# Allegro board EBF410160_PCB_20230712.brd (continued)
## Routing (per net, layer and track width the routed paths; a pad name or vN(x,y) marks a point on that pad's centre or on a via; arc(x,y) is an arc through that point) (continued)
UART9_RX_M1: length 97.9
  TOP w0.156: R225.2 v1(111.38,22.35) ; v1(53.63,59.09) 54.13,59.59 J7.21
  BOTTOM w0.156: v1(111.38,22.35) 109.73,20.7 109.73,15.49 109.09,14.86 80.77,14.86 80.01,15.62 80.01,19.43 79.25,20.19 79.25,23.62 61.59,41.27 59.69,41.27 52.7,48.26 52.7,57.4 53.63,58.33 v1(53.63,59.09)
UART9_TX_M1: length 95.9
  TOP w0.156: J7.19 v1(53.63,60.11) ; R226.2 v1(110.36,22.35)
  BOTTOM w0.156: v1(53.63,60.11) 54.11,59.63 54.11,58.18 53.15,57.21 53.15,48.57 60.03,41.7 61.9,41.7 79.88,23.73 79.88,20.32 80.64,19.55 80.64,15.87 81.15,15.37 108.84,15.37 109.22,15.75 109.22,21.21 v1(110.36,22.35)
USB2_HOST2_DM: length 45.1
  TOP w0.158: v1(92.48,33.4) 92.25,33.17 92.25,32.42 92.49,32.18 93.15,32.18 R126.1 ; J7.74 67.13,56.46 67.06,56.39 67.06,48.39 67.34,48.1 67.34,47.37 v1(67.46,47.24)
  BOTTOM w0.158: v1(67.46,47.24) 71.63,47.24 74.03,44.85 arc(74.12,44.81) 74.21,44.85 arc(74.31,44.89) 74.4,44.85 74.66,44.59 arc(74.7,44.5) 74.66,44.4 arc(74.62,44.31) 74.66,44.21 82.68,36.19 90.3,36.19 90.45,36.04 arc(90.55,36) 90.64,36.04 arc(90.74,36.08) 90.83,36.04 91.09,35.78 arc(91.13,35.69) 91.09,35.59 arc(91.05,35.5) 91.09,35.4 91.35,35.14 arc(91.44,35.11) 91.54,35.14 arc(91.63,35.18) 91.73,35.14 91.99,34.89 arc(92.02,34.79) 91.99,34.7 arc(91.95,34.6) 91.99,34.51 92.31,34.19 92.31,33.57 v1(92.48,33.4)
USB2_HOST2_DP: length 45.1
  TOP w0.158: v1(91.82,33.4) 91.89,33.33 91.89,32.27 92.34,31.82 93.15,31.82 R125.1 ; J7.72 66.63,56.43 66.69,56.37 66.69,48.24 66.98,47.95 66.98,47.42 v1(66.8,47.24)
  BOTTOM w0.158: v1(91.82,33.4) 91.95,33.53 91.95,34.04 90.15,35.83 82.53,35.83 71.48,46.88 67.79,46.88 67.67,46.76 67.26,46.76 66.98,47.04 66.98,47.07 v1(66.8,47.24)
USB2_HOST3_DM: length 45.8
  TOP w0.158: R142.2 98.41,48.37 97.49,48.37 arc(97.39,48.41) 97.35,48.5 arc(97.31,48.6) 97.21,48.64 96.85,48.64 arc(96.76,48.6) 96.72,48.5 arc(96.68,48.41) 96.58,48.37 90.4,48.37 89.92,47.88 70.36,47.88 69.09,46.61 65.91,46.61 65.56,46.96 65.56,52.78 arc(65.59,52.86) 65.67,52.89 arc(65.75,52.92) 65.79,53 65.79,53.41 arc(65.75,53.49) 65.67,53.52 arc(65.59,53.56) 65.56,53.63 65.56,54.04 arc(65.59,54.12) 65.67,54.15 arc(65.75,54.19) 65.79,54.27 65.79,54.68 arc(65.75,54.75) 65.67,54.79 arc(65.59,54.82) 65.56,54.9 65.56,56.3 65.63,56.37 J7.68
USB2_HOST3_DP: length 45.5
  TOP w0.158: R141.2 98.56,48 90.55,48 90.07,47.52 70.51,47.52 69.24,46.25 65.76,46.25 65.2,46.81 65.2,56.3 65.13,56.37 J7.66
USB3_HOST1_DM: length 89.2
  TOP w0.158: v1(93.98,41.2) 93.85,41.07 93.85,40.51 93.47,40.13 92.45,40.13 92.05,40.53 78.63,40.53 70.74,32.64 48.64,32.64 43.56,27.55 43.56,25.94 43.63,25.87 J4.80
  BOTTOM w0.158: v1(93.98,41.2) 93.85,41.33 93.85,45.08 97.9,49.13 97.9,62.76 94.87,65.78 94.87,67.19 R136.2
USB3_HOST1_DP: length 89.2
  TOP w0.158: v1(93.32,41.2) 93.49,41.03 93.49,40.66 93.32,40.49 92.6,40.49 92.2,40.89 78.48,40.89 70.59,33 48.49,33 43.2,27.7 43.2,25.94 43.13,25.87 J4.78
  BOTTOM w0.158: v1(93.32,41.2) 93.49,41.37 93.49,45.23 97.54,49.28 97.54,62.61 94.51,65.64 94.51,67.3 R137.2
USB3_HOST1_SSRXN: length 107.4
  TOP w0.158: v1(90.42,42.8) 90.55,42.93 90.55,43.17 90.39,43.33 78.12,43.33 69.6,34.8 43.13,34.8 38.56,30.23 38.56,29.94 arc(38.6,29.83) 38.71,29.79 arc(38.82,29.75) 38.86,29.64 38.86,29.31 arc(38.82,29.2) 38.71,29.16 arc(38.6,29.11) 38.56,29.01 38.56,28.67 arc(38.6,28.57) 38.71,28.52 arc(38.82,28.48) 38.86,28.37 38.86,28.04 arc(38.82,27.93) 38.71,27.89 arc(38.6,27.85) 38.56,27.74 38.56,25.94 38.63,25.87 J4.60
  BOTTOM w0.158: v1(90.42,42.8) 90.6,42.97 90.6,44.12 96.54,50.06 96.54,56.49 95.89,57.15 95.89,62.23 94.74,63.37 arc(94.61,63.43) 94.48,63.37 arc(94.36,63.32) 94.23,63.37 94.04,63.57 arc(93.98,63.7) 94.04,63.82 arc(94.09,63.95) 94.04,64.07 92.9,65.21 92.9,70 92.83,70.07 U18.2 U18.9 92.83,71.67 92.97,71.81 92.97,73.02 91.67,74.31 90.92,74.31 90.45,74.78 90.45,76.38 90.91,76.85 90.91,77.49 90.45,77.96 90.45,78.71 90.29,78.87 J18.5
USB3_HOST1_SSRXP: length 107.4
  TOP w0.158: J4.58 38.13,25.87 38.2,25.94 38.2,30.37 42.98,35.16 69.45,35.16 77.97,43.69 90.56,43.69 90.93,43.32 90.93,42.95 v1(91.08,42.8)
  BOTTOM w0.158: v1(91.08,42.8) 90.96,42.92 90.96,43.97 96.9,49.91 96.9,56.64 96.25,57.3 96.25,62.38 93.26,65.36 93.26,70 93.33,70.07 U18.1 U18.10 93.33,73.17 91.82,74.67 91.07,74.67 90.81,74.93 90.81,76.23 91.27,76.7 91.27,77.64 90.81,78.1 90.81,78.62 91.06,78.87 J18.6
USB3_HOST1_SSTXN: length 95.4
  TOP w0.158: J4.64 39.63,25.87 39.56,25.94 39.56,27.03 40.09,27.56 arc(40.2,27.61) 40.31,27.56 arc(40.41,27.52) 40.52,27.56 40.75,27.8 arc(40.8,27.91) 40.75,28.01 arc(40.71,28.12) 40.75,28.23 40.99,28.46 arc(41.09,28.5) 41.2,28.46 arc(41.31,28.42) 41.42,28.46 41.65,28.69 arc(41.69,28.8) 41.65,28.91 arc(41.6,29.01) 41.65,29.12 41.88,29.36 arc(41.99,29.4) 42.1,29.36 arc(42.2,29.31) 42.31,29.36 42.54,29.59 arc(42.59,29.7) 42.54,29.8 arc(42.5,29.91) 42.54,30.02 42.75,30.22 arc(42.85,30.26) 42.96,30.22 arc(43.07,30.17) 43.17,30.22 43.41,30.45 arc(43.45,30.56) 43.41,30.67 arc(43.36,30.77) 43.41,30.88 46.33,33.8 70.25,33.8 78.33,41.88 95.79,41.88 96.14,41.52 96.14,41.29 v1(96.05,41.2)
  BOTTOM w0.158: v1(96.05,41.2) 96.16,41.31 96.16,46.25 98.57,48.66 98.57,63.93 96.54,65.96 96.54,67.3 C112.2
USB3_HOST1_SSTXP: length 95.4
  TOP w0.158: J4.62 39.13,25.87 39.2,25.94 39.2,27.18 46.18,34.16 70.1,34.16 78.18,42.24 95.94,42.24 96.52,41.66 96.52,41.39 v1(96.71,41.2)
  BOTTOM w0.158: C113.2 96.9,67.19 96.9,66.11 98.93,64.08 98.93,48.51 96.52,46.1 96.52,41.39 v1(96.71,41.2)
USB20_HOST_PWR_EN: length 82.2
  TOP w0.156: v1(66.17,72.01) 72.01,66.17 72.01,65.53 70.74,64.26 70.74,60.83 69.53,59.63 66.1,59.63 65.63,60.09 J7.67
  ART03 w0.142: v1(108.58,85.73) 107.18,84.33 89.41,84.33 88.01,85.72 88.01,86.87 87.25,87.63 67.31,87.63 66.17,86.49 v1(66.17,72.01)
  BOTTOM w0.156: R140.1 v1(108.58,85.73)
USB20_OTG_PWR_EN: length 64.8
  TOP w0.156: J4.37 v1(33.13,22.1)
  ART03 w0.142: v1(16.13,46.73) 16.13,40.51 17.4,39.24 17.4,35.05 20.93,31.52 29.44,31.52 33.15,27.81 33.15,23.87 33.66,23.37 33.66,22.62 v1(33.13,22.1)
  BOTTOM w0.156: v1(16.13,46.73) 22.86,46.73 23.62,47.5 23.62,57.28 24,57.66 24,64.13 24.76,64.89 R149.1
USB30_HOST_PWR_EN: length 100.5
  TOP w0.156: J5.14 27.13,58.72 26.16,59.69 24,59.69 v1(23.5,59.18)
  ART03 w0.142: v1(89.53,85.74) 89.53,87.37 88.27,88.64 57.66,88.64 57.28,88.26 57.28,74.06 56.93,73.7 36.75,73.7 35.69,72.64 35.69,68.71 34.67,67.69 26.29,67.69 24.13,65.53 24.13,59.82 v1(23.5,59.18)
  BOTTOM w0.156: R146.1 v1(89.53,85.74)
USB OTG: length 10.4
  BOTTOM w0.508: R148.1 24,78.74 v1(24.94,77.8) v1(25.77,76.97) 25.77,76.33 25.65,76.21 C124.1 C123.1 25.65,70.41 U24.1
USB_OTG0_DM: length 84
  TOP w0.158: v1(46.48,25.14) 46.48,26.16 47.49,27.17 49.54,27.17 50.06,26.65 50.06,25.94 50.13,25.87 J6.6
  ART03 w0.144: v1(26.59,77.81) 26.59,73.95 20.99,68.34 20.99,45.96 25.5,41.45 42.13,41.45 43.56,40.02 43.56,28.85 44.64,27.77 arc(44.64,27.76) 44.64,27.76 46.48,25.92 v1(46.48,25.14)
  BOTTOM w0.158: v1(26.59,77.81) 26.59,78.27 26.74,78.42 26.74,78.67 R133.2
USB_OTG0_DP: length 85.8
  TOP w0.158: J6.4 49.63,25.87 49.7,25.94 49.7,26.5 49.39,26.81 49.04,26.81 48.77,26.54 48.26,26.54 47.99,26.81 47.64,26.81 46.84,26.01 46.84,25.55 v1(47.24,25.14)
  ART03 w0.144: v1(47.24,25.14) 46.83,25.56 46.83,26.07 46.36,26.54 arc(46.31,26.66) 46.36,26.79 arc(46.41,26.92) 46.36,27.04 46.21,27.2 arc(46.08,27.25) 45.95,27.2 arc(45.83,27.14) 45.7,27.2 45.55,27.35 arc(45.49,27.48) 45.55,27.6 arc(45.6,27.73) 45.55,27.86 45.39,28.01 arc(45.27,28.06) 45.14,28.01 arc(45.01,27.96) 44.89,28.01 43.91,28.99 43.91,29.66 arc(43.95,29.76) 44.05,29.8 arc(44.15,29.85) 44.2,29.95 44.2,30.23 arc(44.15,30.34) 44.05,30.38 arc(43.95,30.42) 43.91,30.52 43.91,30.81 arc(43.95,30.91) 44.05,30.95 arc(44.15,31) 44.2,31.1 44.2,31.38 arc(44.15,31.49) 44.05,31.53 arc(43.95,31.57) 43.91,31.67 43.91,31.96 arc(43.95,32.06) 44.05,32.1 arc(44.15,32.15) 44.2,32.25 44.2,32.53 arc(44.15,32.64) 44.05,32.68 arc(43.95,32.72) 43.91,32.82 43.91,40.16 42.28,41.79 25.64,41.79 21.34,46.1 21.34,68.2 26.94,73.8 26.94,75.02 arc(26.98,75.1) 27.06,75.14 arc(27.14,75.17) 27.18,75.25 27.18,75.59 arc(27.14,75.68) 27.06,75.71 arc(26.98,75.75) 26.94,75.83 26.94,76.17 arc(26.98,76.25) 27.06,76.29 arc(27.14,76.32) 27.18,76.4 27.18,76.74 arc(27.14,76.83) 27.06,76.86 arc(26.98,76.9) 26.94,76.98 26.94,77.48 27.07,77.61 27.07,77.63 v1(27.25,77.81)
  BOTTOM w0.158: v1(27.25,77.81) 27.25,78.27 27.1,78.42 27.1,78.67 R134.2
USB_OTG0_ID: length 88.4
  TOP w0.156: v1(48.13,23.75) 48.64,23.24 50.97,23.24 51.13,23.4 J6.10
  ART03 w0.142: v1(48.13,23.75) 48.64,24.26 48.64,26.03 44.96,29.72 44.96,40.89 43.52,42.34 25.99,42.34 21.97,46.35 21.97,66.55 28.32,72.9 28.32,76.58 29.59,77.85 v1(33.02,77.85)
  BOTTOM w0.156: R135.2 v1(33.02,77.85)
USB_OTG0_VBUSDET: length 102.4
  TOP w0.156: v1(45.59,23.75) 45.59,26.16 47.62,28.19 50.29,28.19 51.63,26.86 J6.12
  ART03 w0.142: v1(22.23,80) 19.68,77.46 19.68,74.17 19.05,73.53 14.86,73.53 13.08,71.75 13.08,53.21 17.65,48.64 17.65,40.38 18.54,39.5 18.54,35.3 20.83,33.02 36.58,33.02 37.21,32.38 37.21,26.41 39.12,24.51 44.83,24.51 v1(45.59,23.75)
  BOTTOM w0.156: v1(22.23,80) R150.1 R148.2
USER_LED: length 137.6
  TOP w0.156: J5.6 25.13,56.22 v1(24.13,55.22) ; v1(112.01,38.73) 111.38,38.1 111.38,37.46 112.22,36.63 117.25,36.63 117.73,36.14 117.73,22.35 119.51,20.57 124.84,20.57 126.37,19.04 R45.2
  ART03 w0.142: v1(112.01,38.73) 111.51,38.23 56.1,38.23 50.77,43.56 26.67,43.56 23.62,46.61 23.62,54.71 v1(24.13,55.22)
WLAN_PWR_EN: length 66.3
  TOP w0.156: J4.45 35.13,22.61 v1(34.63,23.11) ; R128.1 v1(84.79,37.22)
  ART03 w0.142: v1(34.63,23.11) 35.14,22.6 39.5,22.6 41.4,20.7 48.77,20.7 50.67,22.6 50.67,31.07 54.02,34.42 57.96,34.42 60.76,37.22 v1(84.79,37.22)
N03633: length 1.3
  BOTTOM w0.508: C7.1 4.9,61.15 U3.6
N03801: length 3.7
  BOTTOM w0.254: U3.4 3.49,58.23 3.42,58.16 R6.1 C8.2 R4.2
N28501: length 1.3
  BOTTOM w0.381: C28.1 4.71,73.15 4.9,72.96 U5.6
N15118698: length 2.6
  BOTTOM w0.156: U1.4 19.88,42.47 C4.1 R1.2
N15119063: length 1.9
  BOTTOM w0.254: R2.1 18.67,39.16 18.83,39.01 U1.3
N15122947: length 2.4
  BOTTOM w0.156: R3.2 C9.1 14.62,50.43 U2.4
N15123057: length 1.3
  BOTTOM w0.254: U2.3 16.89,51.39 R5.1
N15599533: length 5.1
  TOP w0.156: R96.2 84.07,54.35 85.22,55.5 85.22,57.25 U16.25
N15599537: length 5
  TOP w0.156: R97.2 83.06,54.05 84.84,55.83 84.84,57.06 U16.24
N15599541: length 5.5
  TOP w0.156: U16.23 84.45,56.88 84.45,56.01 83.85,55.4 82.83,55.4 82.04,54.61 R99.2
N15599545: length 5.4
  TOP w0.156: R100.2 81.03,54.1 82.68,55.75 83.57,55.75 84.07,56.26 84.07,56.69 U16.22
N15599549: length 5.3
  TOP w0.156: U16.27 85.98,57.62 85.98,54.74 86.11,54.61 R101.2
N15599553: length 5.1
  TOP w0.156: R102.2 85.09,54.48 85.6,54.99 85.6,57.43 U16.26
N15599792: length 7.1
  TOP w0.254: R94.1 R93.1 84.07,49.27 84.61,48.74 85.7,48.74 86.11,49.15 R95.1 R91.1 R90.2
N15600759: length 3.6
  TOP w0.254: R109.1 R108.1 R106.2 R107.1
N15600826: length 8.6
  TOP w0.156: R111.2 R110.2 91.57,59.43 90.55,60.45 86.11,60.45 U16.31
N15601838: length 7.2
  TOP w0.156: U16.37 85.47,63.2 85.47,65.4 C81.1 85.72,66.17 85.72,67.29 85.57,67.45 Y1.1
N15601846: length 8.5
  TOP w0.156: Y1.3 86.85,68.95 86.11,68.2 86.11,65.92 C82.1 85.92,65.21 85.92,63.09 U16.36
N15602173: length 17.4
  TOP w0.203: U16.12 79.81,58.67 79.25,58.67 v1(78.99,58.93)
  BOTTOM w0.156: v1(78.99,58.93) 78.11,59.82 78.11,62.48 77.61,62.98 R119.2 R120.2 68.27,62.98 D28.2
N15602572: length 9.3
  TOP w0.156: R118.1 92.84,59.18 91.06,60.96 86.05,60.96 U16.32
N15602600: length 2.4
  BOTTOM w0.254: R117.2 R121.2 89.14,59.19 R122.1
N15603170: length 3.2
  BOTTOM w0.635: C83.1 81.49,68.96 J17.1
N15605512: length 3.9
  TOP w0.156: R98.1 84.2,64.27 84.2,63.07 U16.39
N15605755: length 2.4
  TOP w0.203: U16.28 85.99,58.17
  TOP w0.305: 85.99,58.17 v1(86.5,57.67)
  TOP w0.508: v1(86.5,57.67) 86.49,57.66 v1(86.49,56.77)
N15611443: length 2.4
  BOTTOM w0.156: R140.2 C116.1 111.01,86.73 111.14,86.59 U21.4
N15611553: length 1.5
  BOTTOM w0.254: R143.1 110.75,83.7 111.14,84.09 U21.3
N15653247: length 2.4
  BOTTOM w0.156: U24.4 23.9,67.25 23.76,67.11 C122.1 R149.2
N15653357: length 1.7
  BOTTOM w0.156: R152.1 26.92,67.49 26.65,67.76 U24.3
N15653957: length 2.4
  BOTTOM w0.156: U23.4 92.09,86.6 91.95,86.74 C119.1 R146.2
N15654067: length 1.5
  BOTTOM w0.254: R147.1 91.71,83.71 92.1,84.1 U23.3
N15659726: length 4.7
  BOTTOM w0.254: C18.2 6.1,58.23 5.14,59.18 U3.5 ; C18.2 R8.1 ; C18.2 R7.2
N15752445: length 37.6
  TOP w0.762: U25.G4 64.59,84.71 63.83,85.47 58.85,85.47 58.09,84.71 U25.G2 U25.G1 58.09,69.09 57.33,68.32 L9.1
  BOTTOM w0.762: U25.G4 U25.G3
N15772454: length 3.7
  TOP w0.156: J22.14 128.4,48.53 127.27,49.66 R161.2
N15774097: length 5.9
  TOP w0.156: J21.14 127.52,70.62 127.13,70.23 R160.2
N15830872: length 16.5
  TOP w0.203: v1(38.15,71.49) 39.26,71.49 C176.2
  BOTTOM w0.203: v1(38.15,71.49) D43.2 35.81,73.14 35.81,80.01 36.48,80.68 J28.5 39.94,78.88 J28.3
N15830941: length 18.8
  TOP w0.203: C175.2 32.37,71.49 v1(33.36,71.49)
  BOTTOM w0.203: v1(33.36,71.49) R215.2 D42.2 35.1,71.54 35.1,80.95 38.53,84.38 J28.2
N15838979: length 8.4
  TOP w0.254: J28.4 42.7,74.78 43.81,73.66 R214.2
N15851038: length 3.5
  TOP w0.254: R212.2 C171.1 45.85,65.53 46.35,65.02 R213.1
N15980269: length 5.8
  TOP w0.254: J13.2 69.6,17.27 66.26,17.27 R73.2
N16735828: length 1.8
  TOP w0.156: R45.1 LED2.1
N16735933: length 1.8
  TOP w0.156: R48.1 LED3.1
N16793147: length 7.4
  BOTTOM w0.156: R60.2 116.96,23.37 118.36,23.37 D15.2 119.76,24 121.5,22.26 J12.1
N16793149: length 7.2
  BOTTOM w0.156: R64.2 116.81,29.74 116.9,29.65 118.42,29.65 D19.2 119.38,30.22 120.74,28.86 J12.7
N16793151: length 8
  BOTTOM w0.156: R63.2 117.02,28.38 118.29,28.38 D18.2 119.51,29.08 120.14,28.45 120.14,28.07 121.55,26.66 J12.5
N16793153: length 7.4
  BOTTOM w0.156: R62.2 116.9,25.72 118.42,25.72 D17.2 119.51,26.29 121.34,24.46 J12.3
N16793155: length 7.4
  BOTTOM w0.156: R61.2 116.9,24.57 118.42,24.57 D16.2 119.51,25.14 121.29,23.36 J12.2
N16793157: length 7.2
  BOTTOM w0.156: R65.2 116.81,30.88 116.9,30.8 118.42,30.8 D20.2 119.51,31.37 120.91,29.96 J12.8
N16793300: length 7.2
  BOTTOM w0.156: R66.2 116.81,32.03 116.9,31.94 118.42,31.94 D21.2 119.44,32.51 120.89,31.06 J12.9
N16795570: length 1.8
  TOP w0.156: R49.1 LED4.1
N16795883: length 5.5
  BOTTOM w0.254: U5.5 5.14,71.12 5.63,70.63 5.63,69.7 5.59,69.67 C37.2 ; C37.2 R25.1 R23.2 ; C37.2 R24.2
N16811933: length 7
  TOP w0.156: J27.1 116,69.77 115.67,69.44 v1(112.52,69.44)
  BOTTOM w0.156: v1(112.52,69.44) R206.2 R205.2
N16823854: length 5.6
  TOP w0.156: J27.7 113.6,72.45 113.79,72.64 v1(113.79,72.65)
  BOTTOM w0.156: R207.2 113.54,72.39 113.79,72.64 v1(113.79,72.65)
N16928945: length 2.5
  TOP w0.156: v1(105.2,64.51) J27.20
  BOTTOM w0.156: R208.1 105.66,64.05 v1(105.2,64.51)
N16929135: length 2.4
  TOP w0.156: J27.22 v1(104.4,64.51)
  BOTTOM w0.156: v1(104.4,64.51) 104.65,64.27 R209.1
N16980859: length 9.8
  BOTTOM w0.156: U36.2 119.38,42.8 119.12,42.54 U37.6 119.12,41.65 118.78,41.31 117.38,41.31 116.97,40.9 116.97,39.65 116.81,39.5 C164.1 R199.2
N16980861: length 9.7
  BOTTOM w0.156: R200.2 C163.1 117.68,42.2 U37.4 118.12,43.44 118.74,44.07 120.4,44.07 121.67,45.34 U36.3
N16980863: length 10.2
  BOTTOM w0.156: R198.2 R202.2 C162.1 117.21,41.65 118.46,41.65 118.62,41.81 U37.5 118.62,42.92 119.13,43.43 120.77,43.43 121.41,44.07 U36.7
N17405290: length 3.8
  BOTTOM w0.156: R20.2 C29.2 R22.1 4.83,70.1 U5.4
N17423559: length 1.3
  BOTTOM w0.508: C19.1 4.9,49.21 U4.6
N17423608: length 4.5
  BOTTOM w0.254: R14.2 R15.1 C27.2 5.59,45.79 5.63,45.83 5.63,46.76 5.14,47.24 U4.5
N17423737: length 3.8
  BOTTOM w0.254: U4.4 3.74,46.29 R13.1 C20.2 R11.2
N17430242: length 1.5
  BOTTOM w0.156: U7.3 11.96,36.81 12.07,36.7 R33.1
N17430314: length 2.5
  BOTTOM w0.156: U7.4 12.58,34.31 C44.1 R32.2
N17443353: length 1.5
  BOTTOM w0.156: U6.3 11.83,32.24 11.94,32.13 R31.1
N17443371: length 2.5
  BOTTOM w0.156: U6.4 12.58,29.74 C41.1 R30.2
N17444423: length 7.1
  BOTTOM w0.156: Q5.1 12.2,42.13 C38.2 R27.2 12.2,44.14 12.89,44.83 14.07,44.83 Q6.3
N17444523: length 5.5
  BOTTOM w0.156: Q6.1 16.26,43.65 16.26,42.8 15.76,42.3 R29.1 R28.2
N17454508: length 2.4
  BOTTOM w0.305: C69.2 25.28,44.32 U13.1
N17454513: length 2.4
  BOTTOM w0.305: U13.3 27.82,44.31 C69.1
N17455367: length 2
  BOTTOM w0.305: U13.4 29.09,43.06 C70.2
N17455372: length 2.1
  BOTTOM w0.305: U13.5 30.36,44.82 C70.1
N17455499: length 2.3
  BOTTOM w0.305: U13.6 31.62,44.44 C68.1
N17455508: length 4.2
  BOTTOM w0.305: C66.1 24.25,41.53 26.29,41.53 26.54,41.78 U13.2
N17592125: length 1.4
  BOTTOM w0.508: C154.1 110.43,53.53 U35.6
N17592172: length 3.5
  BOTTOM w0.203: U35.4 109.4,50.36 R203.1 C155.2 R201.2
N17592220: length 4
  BOTTOM w0.156: R204.2 110.86,49.66 111.25,50.05 111.25,50.66 110.61,51.31 U35.5
N17633217: length 5.4
  TOP w0.156: Y2.1 104.76,58.91 104.03,58.18 104.03,56.38 C117.1 104.01,55.87 U22.3
N17633237: length 4.4
  TOP w0.156: Y2.3 103.34,57.41 103.63,57.12 103.63,56.52 C118.2 103.51,55.87 U22.4
N17633305: length 2.1
  TOP w0.156: U22.16 v1(104.01,48.64)
  BOTTOM w0.156: R144.2 104.01,48.64 v1(104.01,48.64)
N17633317: length 2.1
  TOP w0.156: U22.18 v1(105.01,48.64)
  BOTTOM w0.156: R145.2 105.03,48.66 v1(105.01,48.64)
N17685591: length 12.1
  TOP w0.156: Q13.3 123.19,29.21 122.94,29.46 121.16,29.46 120.9,29.72 C151.2 R195.2 119.21,30.36 118.87,30.69 118.87,32.96 119.21,33.3 Q12.1
N17685601: length 2.6
  TOP w0.156: Q13.1 121.39,26.19 R197.1 R196.2
N17690217: length 1.5
  BOTTOM w0.254: R194.1 117.07,34.66 U34.3
N17690290: length 2.7
  BOTTOM w0.156: R192.2 C148.1 113.48,35.12 U34.4
N17695706: length 8.8
  TOP w0.156: C133.1 121.66,58.81 122.24,58.23 U28.4 ; C133.1 R171.2 ; C133.1 120.27,59.44 120.27,62.36 120.54,62.63 U30.4
N17695791: length 1.6
  TOP w0.381: R174.1 121.65,65.13 U30.3
N17695827: length 1.5
  TOP w0.381: U28.3 121.31,60.56 R173.1
N17697466: length 3.9
  BOTTOM w0.381: J17.13 72.7,84.97 R114.1
N17697880: length 1.4
  BOTTOM w0.254: R181.1 123.57,62.23 123.93,62.59 U32.3
N17697953: length 3.2
  BOTTOM w0.156: R179.2 C140.1 122.56,62.86 122.36,63.06 U32.4
N17701231: length 2.7
  TOP w0.254: R74.2 63.33,16 J14.2
N17702194: length 5.3
  BOTTOM w0.254: R81.2 42.42,13.12 42.42,15.87 42.67,16.13 44.1,16.13 J15.3
N17702199: length 5.2
  BOTTOM w0.254: R82.2 41.91,13.12 41.91,15.86 41.66,16.12 J15.4
N17702222: length 5.2
  BOTTOM w0.254: R80.2 49.53,13.12 49.53,15.86 49.28,16.12 J15.2
N17702231: length 5.4
  BOTTOM w0.254: J15.1 50.19,16.12 49.94,15.86 49.94,13.22 R79.2
N17728858: length 3.7
  BOTTOM w0.254: D22.1 55.63,36.96 54.74,36.07 R71.1
N17729021: length 3.8
  BOTTOM w0.254: D23.1 47.24,36.85 46.46,36.07 R72.1
N17731599: length 15.8
  BOTTOM w0.305: R59.2 21.72,23.84 21.72,20.83 19.3,18.41 14.77,18.41 J11.6
N17731608: length 19.1
  BOTTOM w0.305: J11.4 22.16,18.19 29.51,18.19 30.05,18.72 30.05,24.31 29.25,25.11 R58.2
N17731627: length 12.8
  BOTTOM w0.305: R56.2 35.43,24.47 35.43,16.76 34.79,16.12 J11.1
N17748815: length 2.1
  BOTTOM w0.635: Q5.2 11.43,39.46 R26.2
N17750545: length 3.2
  TOP w0.156: Q2.3 23.52,69.21 R12.2 24.96,69.66 Q1.1
N17750554: length 8.8
  TOP w0.508: Q1.3 27.85,70.57 26.92,71.5 D2.1 25.32,73.84 J2.1
N17750632: length 5.2
  TOP w0.156: R17.2 R18.1 21.84,66.68 21.84,68.81 Q2.1
N17759502: length 10.9
  TOP w0.381: D9.3 18.69,67.72 18.28,67.3 C65.1 v1(18.28,65.66)
  BOTTOM w0.381: v1(18.28,65.66) 18.28,69.35 16.76,70.86 U12.8
N17770939: length 5.4
  TOP w0.158: U22.15 103.51,49.28 103.38,49.15 103.38,48.51 102.87,48 100.07,48 R141.1
N17770942: length 5.1
  TOP w0.158: U22.14 103.01,48.66 102.72,48.37 101.33,48.37 arc(101.23,48.41) 101.19,48.5 arc(101.15,48.6) 101.05,48.64 100.69,48.64 arc(100.6,48.6) 100.56,48.5 arc(100.52,48.41) 100.42,48.37 100.21,48.37 R142.1
N17861933: length 4.6
  TOP w0.381: v1(124.21,10.29) U11.2
  BOTTOM w0.381: v1(124.21,10.29) 124.21,11.31 C63.1 C64.1 R47.1
N17863087: length 3.6
  TOP w0.156: U11.3 v1(125.48,10.29)
  BOTTOM w0.156: v1(125.48,10.29) 125.86,10.67 R46.2 R44.2
N17946485: length 8.1
  TOP w0.156: SW3.4 SW3.3 4.28,57.5 D7.2 C60.1 4.82,55.88 R41.1
N17975561: length 4.8
  TOP w0.381: R51.1 R50.2 17.03,71.01 D10.2 16.87,72.16 J10.1
N18056005: length 4
  TOP w0.156: Q7.1 88.46,38.67 R127.2 C107.2 R128.2
N18056634: length 11.4
  TOP w0.483: U17.2 106.93,29.34 arc(105.4,28.71) 104.77,27.18 C105.1
  TOP w0.508: C105.1 104.78,24 C104.1
N18056637: length 2.7
  TOP w0.483: C104.2 104.77,21.72 C106.1 104.78,20.44 CN1.1
N18057325: length 5
  TOP w0.158: U17.7 97.9,32.5 97.67,32.27 94.72,32.27 R126.2
N18057335: length 5
  TOP w0.158: R125.2 94.89,31.91 97.63,31.91 97.9,31.64 U17.6
N18091011: length 1.6
  TOP w0.381: D9.1 16.01,70.31 R50.1
N18111918: length 9.3
  TOP w0.156: U31.4 120.42,41.93 120.14,41.65 120.14,38.35 120.39,38.11 C130.1 ; U29.4 122.24,37.55 121.68,38.11 C130.1 ; C130.1 R170.2
N18111989: length 1.6
  TOP w0.254: R175.1 121.65,44.43 U31.3
N18112037: length 1.5
  TOP w0.381: R172.1 121.31,39.86 U29.3
N18115454: length 4.7
  BOTTOM w0.156: U33.3 123.64,49.59 122.94,48.89 121.02,48.89 R187.1
N18115527: length 3.1
  BOTTOM w0.156: R186.2 C143.1 121.34,49.59 U33.4
N18173560: length 12.8
  TOP w0.635: J19.C2 J19.C1
  BOTTOM w0.508: J19.C3 J19.C1
N18175084: length 1.6
  BOTTOM w0.156: D29.3 32.52,80.01 R135.1
N18245213: length 9.6
  TOP w0.254: LED1.1 7.29,48.51 7.54,48.26 10.41,48.26 11.3,47.37 Q3.3
N18245628: length 1.8
  TOP w0.254: LED1.2 R16.2
N18246356: length 2.4
  TOP w0.156: Q3.1 10.35,40.08 R21.1 R19.2
N18288623: length 8.8
  TOP w0.156: R227.1 R43.1 C61.1 D8.2 3.67,48.55 4.27,49.14 SW4.3 SW4.4
N18353176: length 4.1
  BOTTOM w0.381: J17.12 78.83,84.97 R115.1
N18355550: length 16.1
  BOTTOM w0.305: J11.3 25.31,17.52 31.24,17.52 32.3,18.58 32.3,23.71 32,24 R57.2
N18579208: length 15.7
  TOP w0.156: R219.1 95.63,19.69 95.63,18.3 D48.2 96.27,13.46 96.01,13.21 91.06,13.21 90,12.15 J33.2
N18579211: length 15
  TOP w0.156: J33.3 92,12.24 92.33,12.57 96.77,12.57 97.28,13.08 D47.2 97.92,18.3 97.92,19.69 R220.1
N18585387: length 6.6
  BOTTOM w0.156: R222.1 D50.2 76.58,12.07 J32.2
N18585389: length 7
  BOTTOM w0.156: R221.1 D49.2 77.6,13.06 J32.3
N18585721: length 12.5
  TOP w0.156: J34.2 102,12.3 101.73,12.57 99.69,12.57 99.31,12.95 D52.2 98.68,18.3 98.68,19.69 R224.1
N18585723: length 13.4
  TOP w0.156: R223.1 100.97,19.69 100.97,18.3 D51.2 100.33,13.71 100.84,13.21 103.63,13.21 104,12.84 J34.3
N18585912: length 13.2
  TOP w0.156: J35.2 114,11.6 113.54,12.06 110.87,12.06 110.36,12.57 D54.2 109.83,18.19 109.83,19.8 109.88,19.84 R226.1
N18585914: length 14.1
  TOP w0.156: R225.1 112.01,19.69 112.01,18.3 D53.2 111.38,13.21 111.89,12.7 115.32,12.7 116,12.02 J35.3

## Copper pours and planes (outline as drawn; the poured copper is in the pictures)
1V05_AVDD_PHY on BOTTOM: 81.92,55.62 81.92,54.99 82.04,54.86 82.55,54.86 82.6,54.91 82.6,56.59 82.55,56.64 81.92,56.64 81.66,56.89 81.66,58.67 80.26,60.07 80.26,61.34 82.42,63.5 82.93,63.5 84.14,62.29 84.96,63.12 84.96,63.37 84.81,63.52 84.61,63.52 84.45,63.37 83.95,63.37 83.57,63.75 83.19,63.75 82.42,64.51 82.17,64.51 79.5,61.85 79.5,59.94 81.03,58.42 81.03,56.51
1V05_DVDD_PHY on BOTTOM: 82.93,56.64 85.85,56.64 85.98,56.51 85.98,56.01 86.23,55.75 86.23,54.99 86.11,54.86 83.57,54.86 83.52,54.91 83.52,55.42 83.31,55.62 82.93,55.62 82.8,55.75 82.8,56.51
1V05_PHY on TOP: 87.12,56.89 87.12,55.75 87,55.62 86.74,55.62 86.61,55.5 86.61,53.72 86.87,53.47 87.88,53.47 88.01,53.59 88.01,55.62 88.14,55.75 89.15,55.75 89.15,56.89
1V05_PHY on BOTTOM: 86.74,55.12 87,55.12 87.12,54.99 87.12,53.08 87,52.96 82.04,52.96 81.92,53.08 81.92,54.48 82.04,54.61 82.55,54.61 82.6,54.56 82.6,53.82 82.7,53.72 85.34,53.72 85.47,53.85 85.47,54.48 85.6,54.61 86.36,54.61 86.61,54.86 86.61,54.99
1V8_DVDD_PHY on TOP: 87.76,51.94 87.76,50.8 87.88,50.67 88.65,50.67 89.66,49.66 92.08,49.66 92.46,49.27 93.22,49.27 93.34,49.4 93.34,50.29 93.22,50.42 90.04,50.42 89.41,51.05 89.41,51.94 89.28,52.07 87.88,52.07
1V8_DVDD_PHY on BOTTOM: 87.33,52.25 88.01,51.56 89.28,51.56 89.41,51.69 89.41,51.94 89.28,52.07 88.39,52.07 88.01,52.45 88.01,54.61 87.33,54.61
3V3_AVDD_PHY on BOTTOM: 81.03,65.02 81.66,64.39 82.17,64.9 82.3,64.9 83.19,64.01 83.44,64.01 83.57,64.13 83.57,64.39 82.09,65.86 80.21,65.86 79.63,65.28 76.96,65.28 76.96,64.01 78.36,64.01 78.74,63.63 78.74,59.82 78.87,59.69 79.12,59.69 79.25,59.82 79.25,61.97 79.76,62.48 79.76,62.61 79.25,63.12 79.25,63.88 80.39,65.02
3V3_DVDD_PHY on TOP: 89.41,54.1 89.41,52.7 89.53,52.58 90.04,52.58 90.17,52.7 90.17,53.34 90.3,53.47 92.08,53.47 92.46,53.08 93.34,53.08 93.34,54.1 93.22,54.23 89.53,54.23
3V3_DVDD_PHY on BOTTOM: 88.27,54.61 88.27,52.83 88.39,52.7 90.04,52.7 90.17,52.83 90.17,54.1 89.94,54.33 89.36,54.33 89.08,54.61
3V3_EDP on TOP: 126.57,25.65 128.42,25.65 128.8,25.27 130.63,25.27 130.63,26.08 129.16,26.08 128.91,26.34 126.57,26.34
3V3_EDP on POW04: 124.21,14.48 125.48,15.75 125.48,23.49 125.35,23.62 124.03,23.62 123.9,23.49 123.9,15.92 123.52,15.54 101.55,15.54 100.46,16.64 56.92,16.64 56.82,16.53 56.82,14.71 57.05,14.48
3V3_IMAGE_1 on TOP: 123.95,66.29 130.63,66.29 130.63,65.48 128.6,65.48 127.13,64.01 125.48,64.01 124.97,64.51 123.83,64.51 123.83,66.17
3V3_IMAGE_2 on TOP: 123.83,45.03 123.83,43.84 124.69,43.84 124.97,43.56 126.24,43.56 126.42,43.38 130.63,43.38 130.63,44.19 127.51,44.19 127,44.7 124.84,44.7 124.51,45.03
5V0_CAM_1 on BOTTOM: 123.32,64.64 125.09,64.64 125.6,64.13 129.03,64.13 129.16,64.26 129.16,66.93 129.79,67.56 131.06,67.56 131.06,68.83 129.54,68.83 128.4,67.69 128.4,65.4 128.27,65.28 123.32,65.28
5V0_CAM_2 on BOTTOM: 123.98,51.21 125.53,51.21 126.01,50.72 131.09,50.72 131.09,52.04 129.79,52.04 129.79,51.56 129.72,51.48 126.92,51.48 126.49,51.92 123.98,51.92
5V0_IMAGE_1 on TOP: 123.83,61.16 123.83,59.94 125.09,59.94 125.48,59.56 128.5,59.56 128.78,59.84 128.78,63.63 129.11,63.96 130.63,63.96 130.63,65.28 128.78,65.28 127.76,64.26 127.76,61.49 127.43,61.16
5V0_IMAGE_2 on TOP: 123.83,40.46 123.83,39.24 124.97,39.24 125.22,38.99 126.24,38.99 126.42,38.81 130.18,38.81 130.63,39.27 130.63,43.18 129.34,43.18 129.34,40.59 129.21,40.46
12V_EDP on TOP: 122.73,34.7 127.23,34.7 127.53,34.39 127.53,32.41 127.66,32.28 130.63,32.28 130.63,34.09 129.03,34.09 128.93,34.19 128.93,35.53 128.5,35.97 122.73,35.97
GND on GND02 (solid shape): 68.08,78.04 67.16,77.18 66.48,77.86 66.41,78.04 66.48,78.22 67.16,78.9
GND on GND02 (solid shape): 85.05,78.22 85.12,78.04 85.05,77.86 84.37,77.18 83.45,78.04 84.37,78.9
GND on TOP: 93.73,53.47 95.89,53.47 96.01,53.59 96.01,54.1 95.89,54.23 93.73,54.23 93.6,54.1 93.6,53.59
GND on TOP: 65.99,62.64 65.99,60.1 66.22,59.87 68.78,59.87 68.88,59.97 68.88,62.58 68.76,62.71 66.07,62.71
GND on TOP: 120.6,60.12 120.6,59.49 121.36,59.49 121.92,58.93 124.71,58.93 124.84,58.8 124.84,57.4 124.97,57.28 127.38,57.28 127.51,57.4 127.51,59.18 127.38,59.31 125.2,59.31 124.82,59.69 123.57,59.69 123.49,59.77 123.49,61.67 123.43,61.73 121.65,61.73 121.39,62 121.39,62.25 121.28,62.36 120.65,62.36 120.52,62.23 120.52,61.59 120.57,61.54 121.44,61.54 121.56,61.42 122.83,61.42 122.89,61.37 122.89,59.74 122.83,59.69 121.69,59.69 121.26,60.12
GND on TOP: 120.52,39.5 120.52,38.86 120.65,38.73 121.41,38.73 122.05,38.1 124.71,38.1 124.84,37.97 124.84,36.7 124.97,36.57 127.38,36.57 127.51,36.7 127.51,38.48 127.38,38.61 125.35,38.61 124.97,38.99 123.65,38.99 123.49,39.14 123.49,40.97 123.32,41.15 121.79,41.15 121.28,41.65 120.65,41.65 120.52,41.53 120.52,40.89 120.65,40.77 122.56,40.77 122.89,40.44 122.89,39.14 122.73,38.99 121.92,38.99 121.41,39.5
GND on TOP: 25.48,23.62 26.24,23.62 26.24,25.78 26.54,26.08 26.54,27.41 26.39,27.56 24.1,27.56 24,27.46 24,26.06 24.13,25.93 25.3,25.93 25.48,25.75
GND on TOP: 129.34,67.82 129.34,66.5 131.24,66.5 131.44,66.29 131.7,66.29 131.83,66.42 131.83,67.69 131.7,67.82
GND on TOP: 88.27,55.24 88.27,53.59 88.39,53.47 88.9,53.47 89.03,53.59 89.03,54.35 89.15,54.48 91.82,54.48 91.95,54.61 91.95,55.12 91.82,55.24 90.17,55.24 90.04,55.37 90.04,57.91 89.92,58.04 89.66,58.04 89.53,57.91 89.53,55.62 89.28,55.37 88.39,55.37
GND on TOP: 129.34,30.07 131.22,30.07 131.32,29.97 131.32,28.32 131.27,28.27 129.34,28.27
GND on TOP: 29.36,59.21 29.36,58.9 29.51,58.75 29.51,56.62 30.25,56.62 30.25,59.08 30.02,59.31 29.46,59.31
GND on TOP: 129.34,27.58 129.34,26.77 131.27,26.77 131.32,26.82 131.32,27.53 131.27,27.58
GND on TOP: 120.52,43.05 120.52,42.42 120.65,42.29 121.28,42.29 121.79,42.8 124.59,42.8 124.84,42.54 124.84,40.89 124.97,40.77 127.25,40.77 127.38,40.89 127.38,43.05 125.09,43.05 124.59,43.56 123.67,43.56 123.49,43.74 123.49,45.03 122.89,45.03 122.89,43.71 122.73,43.56 121.79,43.56 121.28,43.05
GND on TOP: 3.05,8.51 1.25,9.25 0.51,11.05 0.51,86.95 1.25,88.75 3.05,89.49 23.24,89.49 23.24,89.03 23.5,89.03 23.5,88.77 31.37,88.77 31.37,89.49 133.95,89.49 135.75,88.75 136.49,86.95 136.49,11.05 135.75,9.25 133.95,8.51 76.2,8.51 69.98,8.51 ; 13 cut-outs
GND on TOP: 102.62,30.61 102.62,19.94 102.36,19.68 101.73,19.68 101.6,19.56 101.6,15.87 101.73,15.75 108.08,15.75 108.2,15.87 108.2,19.56 107.95,19.81 107.19,19.81 106.93,20.06 106.93,26.29 107.44,26.8 111.89,26.8 112.27,27.18 112.27,30.22 111.76,30.73 102.74,30.73 ; 1 cut-out
GND on TOP: 49.28,62.61 49.28,60.63 49.25,60.6 49,60.6 48.97,60.63 48.97,61.26 48.87,61.37 48.49,61.37 48.39,61.47 48.39,61.77 48.49,61.87 48.87,61.87 48.97,61.97 48.97,62.61 49,62.64 49.25,62.64
GND on TOP: 12.19,62.36 14.73,62.36 14.86,62.48 14.86,63.88 14.73,64.01 12.32,64.01 12.06,63.75 12.06,62.48
GND on TOP: 24.89,63.42 24.89,62.9 24.74,62.75 24.74,60.62 24.01,60.62 24.01,63.08 24.01,63.08 24.01,63.41 24.13,63.52 24.79,63.52
GND on TOP: 128.55,45.52 128.55,44.47 128.63,44.4 131.34,44.4 131.47,44.53 131.47,45.01 131.37,45.11 130.76,45.11 130.68,45.19 130.68,45.64 130.66,45.67 128.7,45.67
GND on TOP: 25.51,21.61 26.27,21.61 26.27,19.42 26.6,19.09 26.6,18.87 26.47,18.74 25.36,18.74 25.2,18.9 25.2,19.13 25.51,19.43
GND on TOP: 120.52,63.75 120.52,63.12 120.57,63.07 121.23,63.07 121.67,63.5 124.71,63.5 124.84,63.37 124.84,61.59 124.97,61.47 127.25,61.47 127.38,61.59 127.38,63.75 125.17,63.75 124.66,64.26 123.6,64.26 123.49,64.36 123.49,65.76 122.89,65.76 122.89,64.34 122.81,64.26 121.89,64.26 121.39,63.75
GND on TOP: 125.22,34.16 125.22,32.38 125.35,32.26 127.13,32.26 127.25,32.38 127.25,34.16 127.13,34.29 125.35,34.29
GND on TOP: 90.17,50.67 91.82,50.67 91.95,50.8 91.95,51.94 91.82,52.07 90.3,52.07 90.17,51.94
GND on TOP: 93.73,49.66 95.89,49.66 96.01,49.78 96.01,50.29 95.89,50.42 93.73,50.42 93.6,50.29 93.6,49.78
GND on TOP: 67.49,58.83 67.49,56.59 67.51,56.56 68.81,56.56 68.91,56.67 68.91,59.26 68.78,59.38 67.46,59.38 67.31,59.23 67.31,59
GND on TOP: 30.23,84.02 30.23,81.33 30.4,81.15 32.31,81.15 32.51,81.36 32.51,82.6 32.31,82.8 31.04,82.8 30.84,83 30.84,84.02 30.83,84.02
GND on TOP: 24.43,84.02 24.43,81.33 24.26,81.15 22.35,81.15 22.23,81.28 22.23,82.68 22.35,82.8 23.7,82.8 23.83,82.93 23.83,84.02
GND on TOP: 9.65,68.58 8.64,67.56 8.64,60.83 8.38,60.58 5.99,60.58 5.74,60.83 5.74,73.4 5.87,73.53 9.4,73.53 9.65,73.28
GND on TOP: 123.7,25.65 126.11,25.65 126.24,25.78 126.24,27.18 126.09,27.33 123.9,27.33 123.7,27.13
GND on BOTTOM: 6.86,47.85 8.03,47.85 8.38,47.5 13.08,47.5 13.34,47.75 13.34,52.2 13.08,52.45 9.27,52.45 9.14,52.32 9.14,50.29 9.02,50.16 6.99,50.16 6.86,50.04
GND on BOTTOM: 44.7,31.75 47.22,31.75 47.4,31.93 47.4,34.87 44.58,34.87 44.58,31.88
GND on BOTTOM: 129.79,78.48 131.11,78.48 131.14,78.51 131.14,80.06 130.96,80.24 129.92,80.24 129.77,80.09 129.77,78.51
GND on BOTTOM: 27.48,20.88 28.14,20.88 28.4,21.13 28.4,22.53 28.5,22.63 29.13,22.63 29.26,22.76 29.26,23.34 29.13,23.47 27.03,23.47 26.92,23.37 26.92,22.73 27.05,22.6 27.66,22.6 27.76,22.5 27.76,21.89 27.48,21.61
GND on BOTTOM: 80.01,62.74 79.5,63.24 79.5,63.88 80.39,64.77 81.03,64.77 81.53,64.26
GND on BOTTOM: 10.74,21.64 10.74,20.17 10.77,20.14 12.47,20.14 12.52,20.19 12.52,21.64 12.47,21.69 10.79,21.69
GND on BOTTOM: 21.82,35.41 21.82,31.95 22.02,31.75 24.46,31.75 24.64,31.93 24.64,35.41 24.49,35.56 21.97,35.56
GND on BOTTOM: 9.93,33.45 9.93,31.57 9.8,31.44 8.69,31.44 8.31,31.06 5.69,31.06 5.51,30.89 5.51,29.18 5.66,29.03 8.38,29.03 8.59,29.23 8.59,30.33 8.81,30.56 12.98,30.56 13,30.58 13,31.06 13.69,31.75 14.63,31.75 14.81,31.93 14.81,33.2 14.48,33.53 10.01,33.53 ; 1 cut-out
GND on BOTTOM: 30,35.56 37.39,35.56 37.59,35.36 37.59,32 37.31,31.72 30.05,31.72 29.9,31.88 29.9,35.46
GND on BOTTOM: 80.52,61.21 80.52,60.07 81.92,58.67 81.92,57.02 82.04,56.89 85.85,56.89 85.98,57.02 85.98,57.78 85.85,57.91 85.6,57.91 85.47,58.04 85.47,59.69 85.6,59.82 86.49,59.82 86.61,59.94 86.61,60.58 86.49,60.7 85.34,60.7 83.06,62.99 82.3,62.99
GND on BOTTOM: 28.63,20.52 29.44,20.52 29.64,20.32 29.64,18.87 29.54,18.77 29.18,18.77 29.06,18.9 29.06,19.33 28.93,19.46 28.7,19.46 28.63,19.53
GND on BOTTOM: 10.74,24.26 10.74,25.63 10.82,25.7 12.55,25.7 12.57,25.68 12.57,23.77 12.37,23.57 9.55,23.57 9.37,23.75 9.37,25.55 9.45,25.63 9.8,25.63 9.86,25.58 9.86,24.23 9.96,24.13 10.62,24.13
GND on BOTTOM: 40.51,31.75 43.03,31.75 43.21,31.93 43.21,34.87 40.39,34.87 40.39,31.88
GND on BOTTOM: 48.9,31.75 51.41,31.75 51.59,31.93 51.59,34.87 48.77,34.87 48.77,31.88
GND on BOTTOM: 53.09,31.75 55.6,31.75 55.78,31.93 55.78,34.87 52.96,34.87 52.96,31.88
GND on BOTTOM: 90.93,86.1 90.93,84.45 91.06,84.33 91.57,84.33 91.69,84.45 91.69,84.96 91.82,85.09 93.09,85.09 93.22,84.96 93.22,83.44 93.98,83.44 93.98,84.96 94.11,85.09 95,85.09 95.38,85.47 97.54,85.47 97.66,85.6 97.66,86.23 97.54,86.36 95.5,86.36 94.87,85.72 91.82,85.72 91.69,85.85 91.69,85.98 91.57,86.1
GND on BOTTOM: 18.36,41.76 18.36,40.46 18.97,40.46 19.56,39.88 20.35,39.88 20.52,39.7 20.52,38.4 20.12,38 19.51,38 19.33,37.82 19.33,35.76 19.46,35.64 20.62,35.64 20.7,35.71 20.7,37.59 21.16,38.05 21.16,39.42 21.13,39.45 21.13,42.09 21.64,42.59 21.64,43.23 21.03,43.23 21.03,42.7 20.5,42.16 20.5,40.82 20.4,40.72 19.46,40.72 18.97,41.2 18.97,41.78 18.85,41.91 18.52,41.91
GND on BOTTOM: 24.13,25.91 26.64,25.91 26.72,25.98 26.72,27.43 26.59,27.56 24.13,27.56 24,27.43 24,26.03
GND on BOTTOM: 26.01,35.41 26.01,31.95 26.21,31.75 28.65,31.75 28.83,31.93 28.83,35.41 28.68,35.56 26.16,35.56
GND on BOTTOM: 24.38,73.53 24.99,73.53 25.1,73.43 25.1,70.53 25.43,70.2 25.43,69.39 25.73,69.09 27,69.09 27,68.32 25.78,68.32 25.55,68.1 25.55,67.18 25.73,67 26.21,67 26.29,66.93 26.29,66.04 26.16,65.91 24.51,65.91 24.38,66.04 24.38,66.98 24.43,67.03 24.69,67.03 24.77,67.11 24.77,69.98 24.26,70.48 24.26,73.4
GND on BOTTOM: 9.93,38.02 9.93,36.14 9.8,36.02 8.69,36.02 8.31,35.64 5.69,35.64 5.51,35.46 5.51,33.76 5.66,33.6 7.77,33.6 8.1,33.93 8.1,34.52 8.71,35.13 12.98,35.13 13,35.15 13,35.64 13.69,36.32 14.63,36.32 14.81,36.5 14.81,37.36 14.73,37.44 13.11,37.44 12.93,37.62 12.93,38.1 10.01,38.1 ; 1 cut-out
GND on BOTTOM: 111.76,63.75 114.3,63.75 114.55,63.5 114.55,63.12 114.68,62.99 116.84,62.99 117.09,62.74 117.09,57.4 117.35,57.15 117.35,51.48 113.87,51.48 113.46,51.89 112.39,51.89 112.39,54.08 112.75,54.43 113.84,54.43 114.17,54.76 114.17,59.69 113.92,59.94 111.91,59.94 111.76,60.1
GND on BOTTOM: 6.86,71.73 7.9,71.73 8.33,71.3 11.76,71.3 11.96,71.5 11.96,74.32 12.19,74.55 15.24,74.55 15.37,74.67 15.37,76.07 15.24,76.2 9.4,76.2 9.14,75.94 9.14,74.65 8.64,74.14 6.96,74.14 6.86,74.04
GND on BOTTOM: 3.05,8.51 1.25,9.25 0.51,11.05 0.51,86.95 1.25,88.75 3.05,89.49 133.95,89.49 135.75,88.75 136.49,86.95 136.49,11.05 135.75,9.25 133.95,8.51 ; 19 cut-outs
GND on BOTTOM: 108.46,15.75 108.58,15.87 108.58,21.21 111,23.62 111,26.54 112.27,27.81 112.27,29.97 111.51,30.73 96.39,30.73 95.25,29.59 81.03,29.59 80.52,29.08 80.52,26.92 82.93,24.51 82.93,16.51 83.69,15.75
GND on BOTTOM: 88.27,57.78 88.27,56.01 88.39,55.88 89.92,55.88 90.04,56.01 90.04,57.78 89.92,57.91 88.39,57.91
GND on BOTTOM: 82.8,53.97 82.85,53.92 85.17,53.92 85.22,53.97 85.22,54.48 85.09,54.61 83.44,54.61 83.31,54.74 83.31,55.12 83.19,55.24 82.93,55.24 82.8,55.12
GND on BOTTOM: 112.73,36.88 112.73,36.27 113.26,36.27 113.77,35.76 115.37,35.76 115.49,35.64 115.49,34.82 115.04,34.37 115.04,33.6 115.62,33.6 115.62,34.21 116.18,34.77 116.18,35.61 116.33,35.76 117.81,35.76 118.03,35.53 118.03,34.95 118.11,34.87 119.94,34.87 120.04,34.97 120.04,35.86 119.68,36.22 118.34,36.22 118.19,36.37 113.94,36.37 113.44,36.88
GND on BOTTOM: 129.13,62.69 130.99,62.69 131.09,62.58 131.09,61.75 129.18,61.75 129.01,61.92 129.01,62.56
GND on BOTTOM: 109.97,86.1 109.97,84.45 110.1,84.32 110.61,84.32 110.73,84.45 110.73,84.96 110.86,85.08 112.13,85.08 112.26,84.96 112.26,81.03 112.52,80.77 114.33,80.77 114.5,80.95 114.5,83.08 114.4,83.18 113.27,83.18 113.02,83.44 113.02,84.96 113.15,85.08 114.04,85.08 114.42,85.46 116.58,85.46 116.7,85.59 116.7,86.23 116.58,86.35 114.54,86.35 113.91,85.72 110.86,85.72 110.73,85.84 110.73,85.97 110.61,86.1
GND on BOTTOM: 6.86,59.79 7.92,59.79 8.41,59.31 13.72,59.31 13.97,59.56 13.97,61.97 14.22,62.23 14.86,62.23 14.99,62.36 14.99,63.88 14.86,64.01 13.46,64.01 13.08,64.39 9.27,64.39 9.14,64.26 9.14,62.36 8.99,62.2 7.01,62.2 6.86,62.05
GND on BOTTOM: 5.33,39.75 5.33,38.23 5.59,37.97 7.87,37.97 8.13,38.23 8.13,39.5 8,39.62 6.6,39.62 6.35,39.88 5.46,39.88
GND on BOTTOM: 16.38,42.29 16.38,40.64 16.51,40.51 17.53,40.51 17.78,40.77 17.78,43.18 17.65,43.31 16.76,43.31 16.64,43.18 16.64,42.54
GND on BOTTOM: 26.26,20.52 27.05,20.52 27.1,20.47 27.1,18.95 26.92,18.77 25.3,18.77 25.25,18.82 25.25,19.2 25.43,19.38 26.11,19.38 26.26,19.53
GND on BOTTOM: 80.9,68.32 82.17,68.32 82.3,68.2 82.3,66.8 82.17,66.67 80.9,66.67 80.77,66.8 80.77,68.2
GND on BOTTOM: 5.21,44.45 5.21,43.31 5.33,43.18 6.86,43.18 6.99,43.31 6.99,44.45 6.86,44.58 5.33,44.58
GND on BOTTOM: 123.19,51.05 123.19,50.37 123.32,50.24 125.3,50.24 125.53,50.01 125.53,49.53 125.63,49.43 128.63,49.43 128.7,49.5 128.7,50.39 128.6,50.49 125.86,50.49 125.5,50.85 123.8,50.85 123.7,50.95 123.7,51.05 123.57,51.18 123.32,51.18
GND on BOTTOM: 121.67,64.31 121.54,64.18 121.54,63.63 121.67,63.5 124.84,63.5 124.97,63.37 124.97,61.34 124.84,61.21 122.3,61.21 122.17,61.09 122.17,60.32 121.79,59.94 121.79,59.05 121.92,58.93 127.25,58.93 127.38,59.05 127.38,63.75 127.25,63.88 125.48,63.88 125.04,64.31
GND on BOTTOM: 105.54,57.15 103,57.15 102.74,56.89 102.74,51.18 102.87,51.05 105.28,51.05 105.54,51.31 105.54,55.37 105.41,55.5 105.41,56.39 105.54,56.51
GND on GND02, POW04, GND05: 0.51,86.95 1.25,88.75 3.05,89.49 133.95,89.49 135.75,88.75 136.49,86.95 136.49,11.05 135.75,9.25 133.95,8.51 3.05,8.51 1.25,9.25 0.51,11.05
GND on ART03: 3.05,8.51 1.25,9.25 0.51,11.05 0.51,86.95 1.25,88.75 3.05,89.49 133.95,89.49 135.75,88.75 136.49,86.95 136.49,11.05 135.75,9.25 133.95,8.51 ; 1 cut-out
GND on ART03: 101.47,20.06 101.47,15.87 101.6,15.75 108.46,15.75 108.58,15.87 108.58,19.68 107.31,20.95 107.31,26.67 107.7,27.05 111.63,27.05 112.27,27.68 112.27,29.97 111.51,30.73 102.87,30.73 102.36,30.22 102.36,20.95
VCC3V3_SD on TOP: 27.51,21.61 28.27,21.61 28.27,19.46 28.6,19.13 28.6,18.87 28.47,18.74 27.36,18.74 27.2,18.9 27.2,19.13 27.51,19.43
VCC3V3_SD on BOTTOM: 27.51,20.5 28.12,20.5 28.12,19.4 28.22,19.3 28.45,19.3 28.6,19.15 28.6,18.9 28.47,18.77 27.33,18.77 27.18,18.92 27.18,19.1 27.51,19.43
VCC3V3_SD on POW04: 27.18,20.32 27.18,18.16 27.3,18.03 80.39,18.03 81.03,18.67 87.63,18.67 92.58,23.62 92.58,30.22 93.47,31.11 112.52,31.11 112.78,30.86 112.78,23.87 112.9,23.75 114.05,23.75 114.17,23.87 114.17,31.37 112.9,32.64 90.68,32.64 90.04,32 90.04,24.26 86.23,20.45 27.3,20.45
VCC3V3_SYS on BOTTOM: 7.37,63.37 8.76,63.37 8.76,64.64 8.89,64.77 13.08,64.77 13.46,64.39 14.86,64.39 14.99,64.51 14.99,66.17 14.86,66.29 7.62,66.29 7.37,66.04
VCC3V3_SYS on POW04: 115.82,61.85 124.46,61.85 124.59,61.72 124.59,58.55 124.33,58.29 121.67,58.29 121.41,58.04 121.41,48.51 122.05,47.88 123.19,47.88 123.7,47.37 123.7,38.73 123.19,38.23 119.13,38.23 118.36,38.99 118.36,50.44 117.91,50.9 113.51,50.9 113.16,50.54 63.5,50.54 63.25,50.8 58.8,50.8 58.55,50.54 24.51,50.54 24.13,50.16 24.13,41.65 24,41.53 19.3,41.53 18.41,42.42 18.41,60.32 17.78,60.96 13.72,60.96 13.08,61.59 13.08,65.53 13.46,65.91 16,65.91 16.38,65.53 16.38,64.39 16.64,64.13 24,64.13 24.77,63.37 24.77,54.99 25.4,54.35 35.43,54.35 35.94,53.85 36.58,53.85 37.08,54.35 115.19,54.35 115.44,54.61 115.44,61.47
VCC5V0_SYS on TOP: 23.88,25.63 23.88,19.63 25.27,19.63 25.27,25.63
VCC5V0_SYS on BOTTOM: 7.37,51.43 8.76,51.43 8.76,52.45 9.02,52.7 13.08,52.7 13.34,52.96 13.34,56.01 13.21,56.13 11.43,56.13 11.18,55.88 11.18,54.61 10.92,54.35 7.62,54.35 7.37,54.1
VCC5V0_SYS on BOTTOM: 23.95,25.65 25.65,25.65 25.78,25.53 25.78,21.97 25.65,21.84 23.95,21.84 23.83,21.97 23.83,25.53
VCC5V0_SYS on POW04: 10.92,11.05 4.57,17.4 4.57,55.88 4.7,56.01 12.7,56.01 12.83,55.88 12.83,48 12.7,47.88 11.3,47.88 11.18,47.75 11.18,30.61 13.08,28.7 24.89,28.7 25.27,28.32 25.27,17.65 26.29,16.64 55.32,16.64 55.47,16.48 55.47,15.75 55.58,15.65 56.46,15.65 56.62,15.49 56.62,14.5 56.9,14.22 124.33,14.22 125.73,15.62 125.73,23.75 125.6,23.87 124.03,23.87 123.9,24 123.9,44.12 123.89,44.13 123.89,47.56 123.32,48.13 122.17,48.13 121.79,48.51 121.79,57.66 122.05,57.91 124.59,57.91 124.84,58.16 124.84,61.72 124.46,62.1 123.06,62.1 122.81,62.36 122.81,66.93 122.94,67.05 126.36,67.05 126.75,66.67 126.75,45.08 128.02,43.81 128.02,13.97 125.73,11.68 70.48,11.68 70.23,11.43 68.71,11.43 68.33,11.05
VCC5V0_SYS_2 on BOTTOM: 22.35,69.34 22.35,71.25 21.84,71.75 21.21,71.75 19.68,73.28 19.68,76.2 19.3,76.58 8.84,76.58 8.74,76.48 8.74,75.31 7.32,75.31 7.32,77.95 7.47,78.1 20.45,78.1 21.56,76.99 21.56,74.27 22.12,73.71 22.94,73.71 23.5,73.15 23.5,70.1 23.62,69.98 24.51,69.98 24.51,69.34
VCC5V0_SYS_2 on BOTTOM: 113.31,87.35 113.31,86 113.92,86 113.92,88.29 113.44,88.77 55.24,88.77 55.12,88.64 55.12,87.76 55.24,87.63 93.98,87.63 94.23,87.37 94.23,86.03 94.28,85.98 94.87,85.98 94.87,87.37 95.12,87.63 113.03,87.63
VCC5V0_SYS_2 on ART03: 13.84,76.71 13.97,76.58 15.24,76.58 15.49,76.83 15.49,80.64 16.38,81.53 34.29,81.53 35.69,82.93 56.26,82.93 56.77,83.44 56.77,88.39 56.64,88.52 55.12,88.52 54.99,88.39 54.99,86.1 54.74,85.85 15.37,85.85 13.84,84.33
VCC5V0_USB20_HOST on BOTTOM: 114.54,85.21 116.56,85.21 116.71,85.06 116.71,80.95 116.54,80.77 114.99,80.77 114.81,80.95 114.81,83.18 114.55,83.43 113.4,83.43 113.27,83.56 113.27,84.7 114.04,84.7
VCC5V0_USB30_HOST on BOTTOM: 95.5,85.22 97.54,85.22 97.66,85.09 97.66,80.01 97.41,79.75 96.9,79.75 96.52,80.14 96.52,83.18 96.27,83.44 94.36,83.44 94.23,83.56 94.23,84.71 95,84.71
VCC_1V8 on TOP: 27.25,19.62 26.49,19.62 26.49,21.67 26.16,22 26.16,22.22 26.29,22.35 27.41,22.35 27.56,22.2 27.56,21.99 27.25,21.69
VCC_1V8 on TOP: 92.33,51.81 92.33,50.93 92.58,50.67 95.89,50.67 96.01,50.8 96.01,51.31 95.89,51.43 93.6,51.43 93.22,51.81
VCC_1V8 on BOTTOM: 26.26,22.35 27.43,22.35 27.56,22.22 27.56,21.97 27.43,21.84 27.1,21.84 26.97,21.72 26.97,20.9 26.37,20.9 26.37,21.77 26.16,21.97 26.16,22.25
VCC_1V8 on POW04: 87.12,25.27 88.39,25.27 88.65,25.53 88.65,39.88 88.39,40.13 33.15,40.13 32.51,39.5 32.51,29.84 31.37,28.7 26.8,28.7 26.16,28.07 26.16,21.84 26.42,21.59 37.85,21.59 38.61,22.35 38.61,35.81 39.24,36.45 85.98,36.45 86.61,35.81 86.61,25.78
VCC_12V on TOP: 11.68,77.09 11.68,73.02 11.43,72.77 10.54,72.77 10.16,72.39 10.16,67.69 9.14,66.67 9.14,56.64 9.4,56.39 12.7,56.39 13.08,56.01 13.08,49.02 12.32,48.26 12.32,42.04 12.57,41.78 14.73,41.78 14.99,42.04 14.99,46.99 15.88,47.88 15.88,58.16 14.86,59.18 12.32,59.18 11.81,59.69 11.81,65.91 12.32,66.42 14.22,66.42 14.22,73.15 13.46,73.91 13.46,77.09
VCC_12V on TOP: 119.58,32.59 119.58,30.99 121.67,30.99 121.79,30.86 121.79,30.61 121.92,30.48 122.94,30.48 123.06,30.61 123.06,32 122.81,32.26 121.54,32.26 121.41,32.38 121.41,32.64 121.28,32.76 119.76,32.76
VCC_12V on BOTTOM: 12.7,44.19 12.7,40.89 12.95,40.64 13.84,40.64 14.22,41.02 14.22,44.19 13.97,44.45 12.95,44.45
VCC_12V on BOTTOM: 112.37,50.72 113.64,50.72 113.72,50.8 113.72,51.13 113.77,51.18 117.22,51.18 117.35,51.05 117.35,49.53 117.2,49.38 113.79,49.38 113.72,49.45 113.72,49.91 113.61,50.01 112.37,50.01
VCC_12V on BOTTOM: 8.41,70.94 11.76,70.94 11.96,70.74 11.96,68.12 11.79,67.94 10.29,67.94 10.03,68.2 10.03,69.59 9.8,69.82 6.86,69.82 6.86,70.51 7.98,70.51
VCC_12V on BOTTOM: 13.72,59.05 13.97,58.8 13.97,57.66 13.72,57.4 8.51,57.4 8.05,57.86 6.86,57.86 6.86,58.57 8.03,58.57 8.51,59.05
VCC_12V on BOTTOM: 8.38,47.12 14.61,47.12 14.86,46.86 14.86,45.46 14.73,45.34 10.29,45.34 9.91,44.96 9.91,43.18 9.78,43.05 8.64,43.05 8.51,43.18 8.51,45.44 8,45.95 6.86,45.95 6.86,46.66 7.92,46.66
VCC_12V on POW04: 118.47,32.13 121.31,32.13 121.51,32.33 121.51,36.65 121.23,36.93 117.63,36.93 117.35,37.21 117.35,49.78 117.22,49.91 113.92,49.91 113.67,49.66 113.67,46.86 113.39,46.58 27,46.58 26.42,46 26.42,37.21 25.27,36.07 17.53,36.07 14.99,38.61 14.99,46.86 14.73,47.12 12.19,47.12 11.94,46.86 11.94,31.37 13.08,30.22 29.72,30.22 31.11,31.62 31.11,40.64 31.62,41.15 90.4,41.15 90.78,40.77 90.78,40.03 90.93,39.88 107.87,39.88 108.23,39.52 108.23,33.96 108.66,33.53 117.07,33.53
VCCA_1V8 on TOP: 26.49,23.57 26.16,23.24 26.16,22.99 26.29,22.86 26.54,22.86 27.25,23.57 27.25,25.63 26.49,25.63
VDD_3V3 on TOP: 92.33,55.62 92.33,54.74 92.58,54.48 95.89,54.48 96.01,54.61 96.01,55.12 95.89,55.24 93.6,55.24 93.22,55.62
VDD_3V3 on BOTTOM: 40.08,41.35 40.08,40.72 41.55,40.72 41.78,40.49 41.78,39.24 41.45,38.91 40.08,38.91 40.08,35.99 40.26,35.81 40.51,35.81 40.64,35.94 40.64,36.83 40.77,36.96 42.04,36.96 42.29,37.21 42.29,40.51 42.49,40.72 46.69,40.72 46.89,40.51 46.89,39.65 47.6,39.65 47.6,40.51 47.8,40.72 55.07,40.72 55.27,40.51 55.27,39.65 55.98,39.65 55.98,41.35
VDD_3V3 on BOTTOM: 106.65,55.88 108.15,55.88 108.28,56.01 108.28,57.12 108.2,57.2 105.99,57.2 105.97,57.17 105.97,56.56 105.99,56.54 106.45,56.54 106.55,56.44 106.55,55.98
VDD_3V3 on BOTTOM: 21.46,39.62 22.07,39.62 22.1,39.6 22.1,37.62 22.2,37.51 23.42,37.51 23.55,37.64 23.55,38.91 23.6,38.96 25.5,38.96 25.6,38.86 25.6,36.6 24.77,35.76 21.69,35.76 21.56,35.64 21.03,35.64 21.01,35.66 21.01,36.68 21.18,36.85 21.18,37.72 21.46,38
VDD_3V3 on POW04: 74.8,9.27 74.8,11.43 125.98,11.43 128.4,13.84 128.4,43.94 127.13,45.21 127.13,66.8 126.49,67.44 122.81,67.44 122.56,67.18 122.56,62.48 122.3,62.23 115.57,62.23 115.19,61.85 115.19,54.99 114.81,54.61 25.53,54.61 25.27,54.86 25.27,63.24 24.13,64.39 16.76,64.39 16.64,64.51 16.64,65.66 16,66.29 13.46,66.29 12.83,65.66 12.83,61.34 13.59,60.58 16.26,60.58 18.16,58.67 18.16,42.16 19.18,41.15 24,41.15 24.13,41.02 24.13,37.08 24,36.96 17.78,36.96 15.88,38.86 15.88,44.32 16.51,44.96 16.51,46.86 15.43,47.94 13.4,47.94 13.21,48.13 13.21,55.88 12.83,56.26 4.7,56.26 4.57,56.39 4.57,68.45 5.21,69.09 118.24,69.09 118.49,69.34 118.49,71.88 119,72.39 130.18,72.39 130.81,71.75 130.81,12.83 127.25,9.27
VDD_5V on BOTTOM: 16.51,53.21 18.16,53.21 18.41,52.96 19.56,52.96 19.81,52.7 20.45,52.7 20.45,54.48 20.32,54.61 16.89,54.61 16.51,54.23
FAN on TOP: 24.64,64.51 25.45,64.51 25.45,65.99 25.58,66.12 26.75,66.12 26.75,68.12 26.64,68.22 24.89,68.22 24.82,68.3 24.82,68.5 24.21,68.5 24.21,67.89 24.56,67.89 24.64,67.82
HUB_3V3 on BOTTOM: 105.94,55.4 105.94,51.21 106.1,51.05 106.93,51.05 107.06,51.18 107.06,54.51 107.21,54.66 108.23,54.66 108.28,54.71 108.28,55.5 108.23,55.55 106.1,55.55
MINIPCIE_3V3 on TOP: 92.1,62.1 92.66,62.1 92.68,62.08 92.68,64.74 93.09,65.15 103,65.15 103.3,64.85 103.3,62 103.15,61.85 102.41,61.85 102.29,61.72 102.29,61.34 102.39,61.24 103.76,61.24 103.91,61.39 103.91,65.89 103.5,66.29 98.7,66.29 97.89,67.11 97.89,72.29 96.52,72.29 96.49,72.26 96.49,67.21 95.58,66.29 92.58,66.29 92.1,65.81
MINIPCIE_3V3 on BOTTOM: 102.23,61.97 102.23,60.96 103.3,59.89 107.34,59.89 108.08,60.63 108.08,62.15 108.28,62.36 110.19,62.36 110.36,62.18 110.36,59.82 110.62,59.56 110.62,58.29 112.9,58.29 112.9,59.69 111.73,59.69 111.51,59.92 111.51,63.63 111.38,63.75 106.43,63.75 106.32,63.65 106.32,61.52 105.97,61.16 104.19,61.16 103.89,61.47 103.89,61.85 103.76,61.97
RS485_1_A on TOP (solid shape): 68.36,16 67.58,15.25 66.86,15.92 66.83,16 66.86,16.08 67.58,16.75
RS485_2_A on TOP (solid shape): 59.93,15.25 59.26,14.53 59.18,14.5 59.1,14.53 58.43,15.25 59.18,16.03
USB OTG on TOP: 24.64,84.02 25.22,84.02 25.22,81.2 25.5,80.92 29.06,80.92 29.41,81.28 29.41,84.02 30.02,84.02 30.02,79.55 28.96,78.48 26.29,78.48 26.04,78.23 26.04,76.83 25.91,76.71 24.77,76.71 24.64,76.83
N02088 on TOP: 6.99,82.42 6.99,73.91 7.11,73.79 8.89,73.79 8.89,78.36 9.14,78.61 10.92,78.61 11.18,78.87 11.18,82.42 10.92,82.68 7.24,82.68
N03641 on BOTTOM: 6.76,59.54 7.75,59.54 7.75,58.83 6.2,58.83 5.59,59.43 5.59,60.58 5.33,60.83 5.33,61.75 5.18,61.9 3.94,61.9 3.71,62.13 3.71,65.68 5.13,65.68 5.13,63.07 5.33,62.86 6.1,62.86 6.6,62.36 6.6,59.69
N28533 on BOTTOM: 6.73,71.47 7.75,71.47 7.75,70.76 6.07,70.76 5.59,71.25 5.59,72.52 5.33,72.77 5.33,73.66 5.18,73.81 3.89,73.81 3.73,73.96 3.73,77.6 5.13,77.6 5.13,74.93 5.38,74.67 6.1,74.67 6.6,74.17 6.6,71.6
N15605755 on BOTTOM: 86.23,57.78 86.23,56.13 86.49,55.88 86.49,55.5 86.61,55.37 87.12,55.37 87.25,55.24 87.25,54.99 87.38,54.86 88.9,54.86 89.03,54.99 89.03,55.5 88.9,55.62 88.14,55.62 88.01,55.75 88.01,57.78 87.88,57.91 86.36,57.91
N17423580 on BOTTOM: 6.76,47.6 7.75,47.6 7.75,46.89 6.2,46.89 5.59,47.5 5.59,48.64 5.33,48.89 5.33,49.68 5.08,49.94 3.86,49.94 3.71,50.09 3.71,53.75 5.13,53.75 5.13,51.13 5.33,50.93 6.1,50.93 6.6,50.42 6.6,47.75
N17466585 on TOP: 85.6,59.56 86.23,58.93 87,58.93 87.12,58.8 87.12,57.66 89.15,57.66 89.15,59.18 88.65,59.69 85.72,59.69
N17592129 on BOTTOM: 112.24,51.66 113.28,51.66 113.28,50.95 111.73,50.95 111.12,51.56 111.12,53.21 111,53.34 111,54.53 110.87,54.66 110.62,54.66 110.62,56.06 112.9,56.06 112.9,54.66 112.39,54.66 112.14,54.41 112.14,51.76
N17685851 on TOP: 123.7,33.78 124.71,33.78 124.71,30.48 123.7,30.48
N17702231 on BOTTOM (solid shape): 51.76,16.12 50.82,15.3 50.09,16.04 50.06,16.12 50.09,16.2 50.82,16.93
N17731627 on BOTTOM (solid shape): 33.18,16.21 33.21,16.12 33.18,16.03 32.42,15.27 31.49,16.12 32.42,16.97
